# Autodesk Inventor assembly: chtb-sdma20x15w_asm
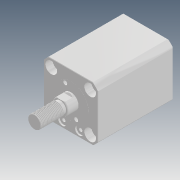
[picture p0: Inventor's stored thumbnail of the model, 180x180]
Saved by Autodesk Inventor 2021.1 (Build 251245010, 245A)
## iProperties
Company: Microsoft
Created: 2018-05
Part Number: chtb-sdma20x15w_asm
Description: STEP AP214
Document SubType Name: Assembly
Designer: user
Title: chtb-sdma20x15w_asm.STEP
Author: Windows
Revision Number: ÈÎºÎ
Sending System: SolidWorks 2015
Preprocessor: SwSTEP 2.0
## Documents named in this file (4)
- D:\Vault_2016\Projekty\Clamptek\Hydraulic\CHTB\CHTB-20\Inventor\CHTB-SDMA20x15W\chtb-sdma20x15w_asm.iam
- D:\Vault_2016\Projekty\Clamptek\Hydraulic\CHTB\CHTB-20\Inventor\CHTB-SDMA20x15W\CHTB-SDMA20X15NBT.ipt
- D:\Vault_2016\Projekty\Clamptek\Hydraulic\CHTB\CHTB-20\Inventor\CHTB-SDMA20x15W\CHTB-SDMA20X15WHSG.ipt
- D:\Vault_2016\Projekty\Clamptek\Hydraulic\CHTB\CHTB-20\Inventor\CHTB-SDMA20x15W\QG_3.ipt
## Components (3 placed, 3 different names)
1. CHTB-SDMA20X15NBT_1
2. CHTB-SDMA20X15WHSG_2
3. QG_3_3
